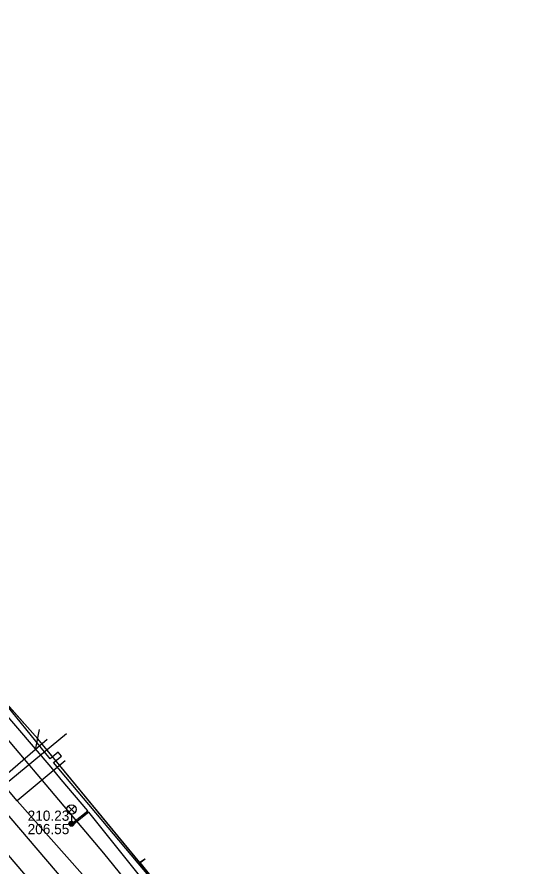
# Model space of a CAD drawing. Extents: x -595540 to -593988, y -1160850 to -1159202.
# Drawn here: x -595314.4 to -595275.3, y -1160803.9 to -1160737.2 of the extents above; entities that cross this region are included whole.
import ezdxf

# ---------------------------------------------------------------- set-up
doc = ezdxf.new("R2010")
doc.units = 0
for name, color, linetype in [('BVK-JEDNOTNA_popisy', 7, 'Continuous'), ('BVK-JEDNOTNA_trasa sítě', 7, 'Continuous'), ('BVK-VODOVOD_trasa sítě', 7, 'Continuous'), ('CETIN_kabel podzemní', 7, 'Continuous'), ('DESTOVA_trasa neprovozované sítě', 7, 'Continuous'), ('DSP-SDEL-VODAFONE_kabel', 7, 'Continuous'), ('EON-NN_kabel', 7, 'Continuous'), ('INNOGY-STL_trasa sítě', 7, 'Continuous'), ('JEDNOTNA_trasa neprovozované sítě', 7, 'Continuous'), ('TSB_kabel VO', 7, 'Continuous'), ('TSB_lampy VO', 7, 'Continuous')]:
    doc.layers.add(name, color=color, linetype=linetype)

msp = doc.modelspace()

# ---------------------------------------------------------------- linework, layer by layer
at = {"layer": 'BVK-JEDNOTNA_popisy'}
msp.add_line((-595313.603, -1160800.43), (-595313.603, -1160800.43), dxfattribs=at)
at = {"layer": 'BVK-JEDNOTNA_trasa sítě'}
msp.add_lwpolyline([(-595312.844, -1160805.652), (-595315.112, -1160803.009)], dxfattribs=at)
at = {"layer": 'BVK-VODOVOD_trasa sítě'}
for points in [[(-595371.95, -1160745.249), (-595366.865, -1160745.817), (-595360.935, -1160746.418), (-595357.631, -1160750.253), (-595353.009, -1160755.617), (-595349.428, -1160759.829), (-595342.068, -1160768.489), (-595341.378, -1160769.3), (-595340.511, -1160770.31), (-595339.773, -1160771.169), (-595333.287, -1160778.721), (-595332.011, -1160780.207), (-595329.559, -1160783.063), (-595326.425, -1160786.719), (-595325.383, -1160787.935), (-595321.785, -1160792.133), (-595319.43, -1160794.881), (-595318.95, -1160795.441), (-595317.724, -1160796.871), (-595316.471, -1160798.334), (-595310.689, -1160805.087)], [(-595316.471, -1160798.334), (-595316.3, -1160798.195), (-595310.541, -1160793.446)]]:
    msp.add_lwpolyline(points, dxfattribs=at)
at = {"layer": 'CETIN_kabel podzemní'}
for points in [[(-595307.62, -1160802.85), (-595318.81, -1160789.62), (-595323.72, -1160784.25), (-595325.83, -1160781.85)], [(-595304.8, -1160803.59), (-595312.81, -1160793.88), (-595317.27, -1160788.86)], [(-595306.05, -1160804.79), (-595307.62, -1160802.85)], [(-595304.41, -1160803.31), (-595304.8, -1160803.59)], [(-595304.8, -1160803.59), (-595302.74, -1160806.18)]]:
    msp.add_lwpolyline(points, dxfattribs=at)
at = {"layer": 'DESTOVA_trasa neprovozované sítě'}
msp.add_line((-595312.705, -1160793.132), (-595313, -1160794.729), dxfattribs=at)
at = {"layer": 'DSP-SDEL-VODAFONE_kabel'}
msp.add_line((-595304.799, -1160803.593), (-595304.377, -1160803.293), dxfattribs=at)
msp.add_lwpolyline([(-595288.613, -1160822.488), (-595292.598, -1160817.872), (-595293.595, -1160816.771), (-595302.742, -1160806.177), (-595304.799, -1160803.593), (-595312.811, -1160793.877), (-595317.268, -1160788.864), (-595321.744, -1160783.867), (-595326.113, -1160778.856), (-595331.116, -1160773.337), (-595335.91, -1160767.874)], dxfattribs=at)
at = {"layer": 'EON-NN_kabel'}
msp.add_lwpolyline([(-595294.118, -1160816.475), (-595311.577, -1160795.738), (-595310.951, -1160795.232), (-595311.077, -1160795.077), (-595311.202, -1160794.921), (-595311.832, -1160795.431), (-595316.021, -1160790.311)], dxfattribs=at)
at = {"layer": 'INNOGY-STL_trasa sítě'}
for points in [[(-595275.27, -1160843.241), (-595278.76, -1160839.33), (-595285.31, -1160831.9), (-595289.42, -1160827.31), (-595293.96, -1160822.16), (-595300.15, -1160815), (-595305.41, -1160808.92), (-595314.42, -1160798.75), (-595318.99, -1160793.35), (-595323.32, -1160788.31), (-595329.47, -1160781.23), (-595339.14, -1160770.17), (-595343.434, -1160765.124), (-595348.96, -1160758.63), (-595350.37, -1160757.03), (-595352.73, -1160754.32), (-595354.58, -1160747.36), (-595357.15, -1160738.49), (-595357.46, -1160737.46), (-595357.542, -1160737.214)], [(-595310.65, -1160795.6), (-595314.42, -1160798.75)]]:
    msp.add_lwpolyline(points, dxfattribs=at)
at = {"layer": 'JEDNOTNA_trasa neprovozované sítě'}
msp.add_lwpolyline([(-595312.06, -1160793.92), (-595313, -1160794.729), (-595318.307, -1160799.294)], dxfattribs=at)
at = {"layer": 'TSB_kabel VO'}
msp.add_lwpolyline([(-595303.47, -1160806.31), (-595308.793, -1160799.617), (-595309.951, -1160800.534), (-595310.081, -1160800.577), (-595310.16, -1160800.54), (-595310.119, -1160800.463), (-595310.009, -1160800.426), (-595308.869, -1160799.524), (-595310.97, -1160797.07), (-595311.75, -1160796.1), (-595315.79, -1160791.42)], dxfattribs=at)
at = {"layer": 'TSB_lampy VO'}
for p, q in [((-595310.425, -1160799.68), (-595309.895, -1160799.15)), ((-595310.425, -1160799.15), (-595309.895, -1160799.68)), ((-595310.425, -1160799.68), (-595309.895, -1160799.15)), ((-595310.425, -1160799.15), (-595309.895, -1160799.68)), ((-595310.16, -1160799.79), (-595310.16, -1160800.54)), ((-595310.16, -1160799.79), (-595310.16, -1160800.54))]:
    msp.add_line(p, q, dxfattribs=at)
for centre, radius in [((-595310.16, -1160799.415), 0.375), ((-595310.16, -1160799.415), 0.375), ((-595310.16, -1160800.54), 0.2), ((-595310.16, -1160800.54), 0.2), ((-595310.16, -1160800.54), 0.145), ((-595310.16, -1160800.54), 0.145), ((-595310.16, -1160800.54), 0.0876), ((-595310.16, -1160800.54), 0.0876)]:
    msp.add_circle(centre, radius, dxfattribs=at)

# ---------------------------------------------------------------- texts
at = {"layer": 'BVK-JEDNOTNA_popisy'}
for s, p in [('210.23', (-595313.603, -1160800.305)), ('206.55', (-595313.603, -1160801.355))]:
    msp.add_text(s, height=0.8, dxfattribs=at).set_placement(p)

doc.saveas('drawing.dxf')
